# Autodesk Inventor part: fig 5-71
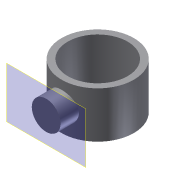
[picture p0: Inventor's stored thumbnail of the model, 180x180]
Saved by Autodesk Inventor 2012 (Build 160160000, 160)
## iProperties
Shininess: 64.0
Length Units: 11269
Angle Units: 11279
Time Units: 11290
Mass Units: 11283
Length Display Precision: 3
Angle Display Precision: 2
Compacted: True
Part Number: fig 5-71
Document SubType Name: Modeling
Created: 2002-12
Designer: deepak
Density: 1 g/cm^3
Material: Default
Density: 0.0
Volumn: 0.0
Area: 0.0
PropertySet Name: Model Information
Control State: 0
Master: False
Checked Out: False
Author: deepak
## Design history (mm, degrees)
sketch "Sketch1"
  geometry: C1 r 23.454 at (0, 0); C2 r 19.43 at (0, 0)
  constraints: 2 centre point, 1 coincident, 1 concentric
extrude "Extrusion1" new body sketch "Sketch1" stored distance "d0" = 30; taper "d1" = 0 deg
workplane "Work Plane1"
workplane "Work Plane2"
sketch "Sketch2"
  geometry: C1 r 9.343 at (0, 0)
  constraints: 1 centre point
extrude "Extrusion2" join sketch "Sketch2" stored distance "d4" = 10; taper "d5" = 0 deg
body "Solid1"
